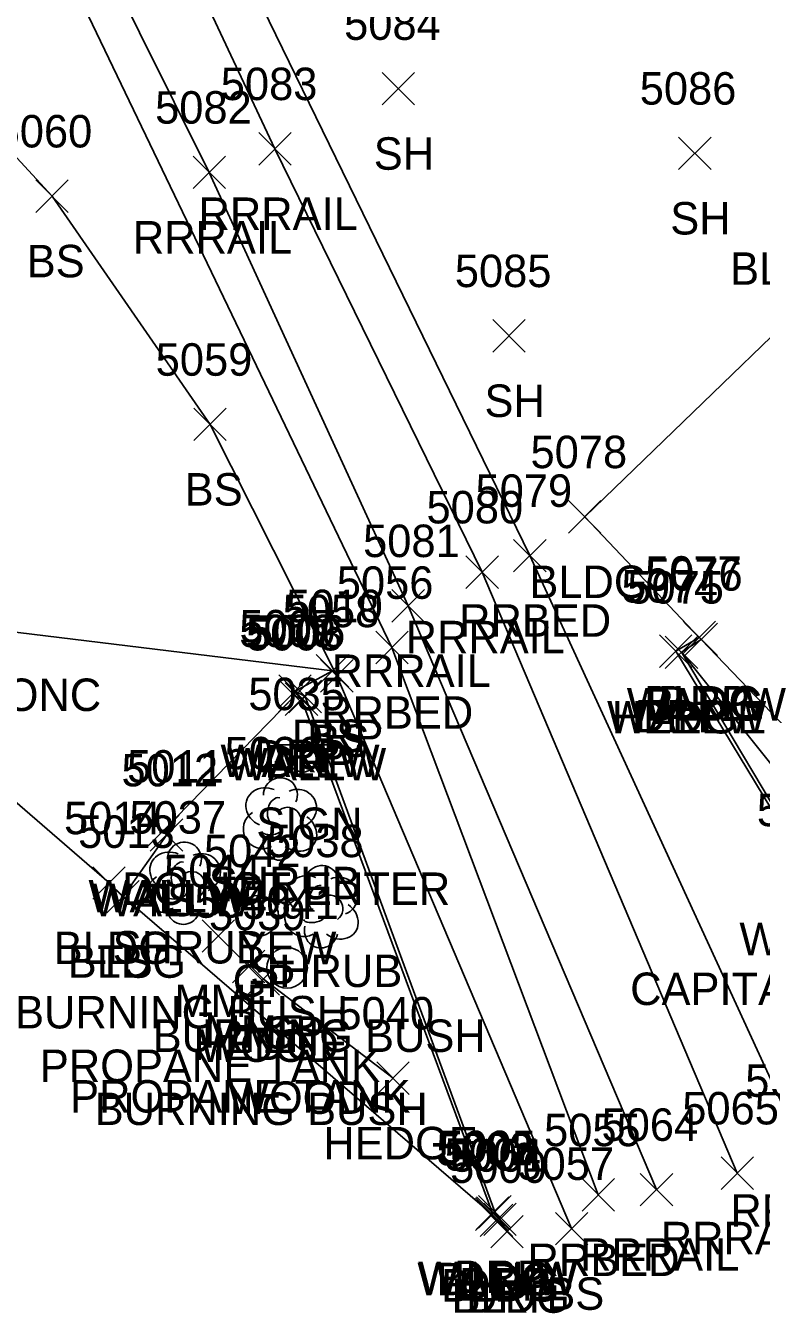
# Model space of a CAD drawing. Extents: x 1618146 to 1620418, y 640749 to 641927.
# Drawn here: x 1620302.7 to 1620347.9, y 640851.8 to 640931.1 of the extents above; entities that cross this region are included whole.
import ezdxf

# ---------------------------------------------------------------- set-up
doc = ezdxf.new("R2010")
doc.units = 0
for name, color, linetype in [('L_A', 7, 'Continuous'), ('L_C', 7, 'Continuous'), ('L_I', 7, 'Continuous'), ('L_TIC', 7, 'Continuous'), ('LAHR', 7, 'Continuous'), ('LBC', 7, 'Continuous'), ('LELB', 7, 'Continuous'), ('LSH', 7, 'Continuous'), ('LW', 7, 'Continuous'), ('R_A', 7, 'Continuous'), ('R_C', 7, 'Continuous'), ('R_I', 7, 'Continuous'), ('R_TIC', 7, 'Continuous'), ('RDP', 7, 'Continuous'), ('RGP', 7, 'Continuous'), ('RR', 7, 'Continuous'), ('RRB', 7, 'Continuous'), ('S_A', 7, 'Continuous'), ('S_C', 7, 'Continuous'), ('S_I', 7, 'Continuous'), ('SSGN', 7, 'Continuous')]:
    doc.layers.add(name, color=color, linetype=linetype)

msp = doc.modelspace()

# ---------------------------------------------------------------- linework, layer by layer
at = {"layer": 'L_TIC'}
for points in [[(1620324.595, 640926.259), (1620326.595, 640928.259)], [(1620326.595, 640926.259), (1620324.595, 640928.259)], [(1620342.854, 640922.27), (1620344.854, 640924.27)], [(1620344.854, 640922.27), (1620342.854, 640924.27)], [(1620303.27, 640919.632), (1620305.27, 640921.632)], [(1620305.27, 640919.632), (1620303.27, 640921.632)], [(1620331.413, 640911.029), (1620333.413, 640913.029)], [(1620333.413, 640911.029), (1620331.413, 640913.029)], [(1620313, 640905.57), (1620315, 640907.57)], [(1620315, 640905.57), (1620313, 640907.57)], [(1620336.076, 640899.875), (1620338.076, 640901.875)], [(1620338.076, 640899.875), (1620336.076, 640901.875)], [(1620343.131, 640892.451), (1620345.131, 640894.451)], [(1620345.131, 640892.451), (1620343.131, 640894.451)], [(1620343.245, 640892.328), (1620345.245, 640894.328)], [(1620345.245, 640892.328), (1620343.245, 640894.328)], [(1620343.245, 640892.328), (1620345.245, 640894.328)], [(1620345.245, 640892.328), (1620343.245, 640894.328)], [(1620342.033, 640891.533), (1620344.033, 640893.533)], [(1620344.033, 640891.533), (1620342.033, 640893.533)], [(1620342.033, 640891.533), (1620344.033, 640893.533)], [(1620344.033, 640891.533), (1620342.033, 640893.533)], [(1620320.542, 640890.388), (1620322.542, 640892.388)], [(1620322.542, 640890.388), (1620320.542, 640892.388)], [(1620320.811, 640890.079), (1620322.811, 640892.079)], [(1620322.811, 640890.079), (1620320.811, 640892.079)], [(1620318.222, 640888.851), (1620320.222, 640890.851)], [(1620320.222, 640888.851), (1620318.222, 640890.851)], [(1620318.631, 640888.646), (1620320.631, 640890.646)], [(1620320.631, 640888.646), (1620318.631, 640890.646)], [(1620310.095, 640880.505), (1620312.095, 640882.505)], [(1620312.095, 640880.505), (1620310.095, 640882.505)], [(1620310.319, 640880.275), (1620312.319, 640882.275)], [(1620312.319, 640880.275), (1620310.319, 640882.275)], [(1620310.319, 640880.275), (1620312.319, 640882.275)], [(1620312.319, 640880.275), (1620310.319, 640882.275)], [(1620306.781, 640877.325), (1620308.781, 640879.325)], [(1620308.781, 640877.325), (1620306.781, 640879.325)], [(1620307.647, 640876.482), (1620309.647, 640878.482)], [(1620309.647, 640876.482), (1620307.647, 640878.482)], [(1620307.647, 640876.482), (1620309.647, 640878.482)], [(1620309.647, 640876.482), (1620307.647, 640878.482)], [(1620313.515, 640874.06), (1620315.515, 640876.06)], [(1620315.515, 640874.06), (1620313.515, 640876.06)], [(1620315.379, 640872.178), (1620317.379, 640874.178)], [(1620317.379, 640872.178), (1620315.379, 640874.178)], [(1620316.279, 640871.411), (1620318.279, 640873.411)], [(1620318.279, 640871.411), (1620316.279, 640873.411)], [(1620324.273, 640865.299), (1620326.273, 640867.299)], [(1620326.273, 640865.299), (1620324.273, 640867.299)], [(1620330.352, 640856.923), (1620332.352, 640858.923)], [(1620332.352, 640856.923), (1620330.352, 640858.923)], [(1620330.352, 640856.923), (1620332.352, 640858.923)], [(1620332.352, 640856.923), (1620330.352, 640858.923)], [(1620330.403, 640856.988), (1620332.403, 640858.988)], [(1620332.403, 640856.988), (1620330.403, 640858.988)], [(1620330.644, 640856.534), (1620332.644, 640858.534)], [(1620332.644, 640856.534), (1620330.644, 640858.534)], [(1620331.284, 640855.845), (1620333.284, 640857.845)], [(1620333.284, 640855.845), (1620331.284, 640857.845)], [(1620335.269, 640856.028), (1620337.269, 640858.028)], [(1620337.269, 640856.028), (1620335.269, 640858.028)]]:
    msp.add_lwpolyline(points, dxfattribs=at)
at = {"layer": 'LAHR'}
for points in [[(1620358.877, 640864.536), (1620354.87, 640877.733), (1620343.033, 640892.533)], [(1620317.279, 640872.411), (1620325.273, 640866.299)]]:
    msp.add_lwpolyline(points, dxfattribs=at)
at = {"layer": 'LBC'}
for points in [[(1620357.188, 640879.802), (1620344.245, 640893.328), (1620344.131, 640893.451), (1620337.076, 640900.875), (1620357.059, 640920.172), (1620360.646, 640923.652), (1620363.762, 640926.588), (1620367.036, 640929.694)], [(1620332.284, 640856.845), (1620331.644, 640857.534), (1620331.352, 640857.923), (1620308.647, 640877.482), (1620307.781, 640878.325), (1620291.579, 640892.357), (1620287.512, 640896.159), (1620282.611, 640900.197), (1620282.333, 640900.011), (1620250.859, 640862.217)]]:
    msp.add_lwpolyline(points, dxfattribs=at)
at = {"layer": 'LELB'}
for points in [[(1620336.269, 640857.028), (1620321.811, 640891.079), (1620314, 640906.57), (1620304.27, 640920.632), (1620296.264, 640929.294)], [(1620311.319, 640881.275), (1620308.647, 640877.482)]]:
    msp.add_lwpolyline(points, dxfattribs=at)
at = {"layer": 'LSH'}
for p, q in [((1620318.291, 640882.32), (1620318.291, 640882.32)), ((1620318.291, 640882.32), (1620318.291, 640882.32)), ((1620312.376, 640878.362), (1620312.376, 640878.362)), ((1620312.376, 640878.362), (1620312.376, 640878.362)), ((1620320.848, 640876.912), (1620320.848, 640876.912)), ((1620320.848, 640876.912), (1620320.848, 640876.912))]:
    msp.add_line(p, q, dxfattribs=at)
for centre in [(1620318.337, 640883.754), (1620312.422, 640879.796), (1620320.895, 640878.346)]:
    msp.add_arc(centre, 1.047, 335.52715, 180.95627, dxfattribs=at)
for centre, major_axis, ratio, start_param, end_param in [((1620317.499, 640882.987), (1.21, -0.512), 0.895232, 1.570796, 4.712389), ((1620319.332, 640882.904), (-1.141, -0.483), 0.949671, 1.570796, 4.712389), ((1620318.082, 640882.778), (-0.208, -0.792), 0.645439, 3.141593, 6.283185), ((1620318.791, 640882.153), (-0.5, 0.667), 0.989748, 3.141593, 6.283185), ((1620317.207, 640881.612), (0.584, -1.042), 0.959034, 3.141593, 6.283185), ((1620319.291, 640881.487), (-1.09, 0.792), 0.841452, 1.570796, 4.712389), ((1620317.832, 640881.57), (-0.625, -0.083), 0.423636, 0, 3.141593), ((1620311.584, 640879.028), (1.21, -0.512), 0.895232, 1.570796, 4.712389), ((1620313.417, 640878.945), (-1.141, -0.483), 0.949671, 1.570796, 4.712389), ((1620318.291, 640880.82), (0.265, 1.061), 0.942809, 1.570796, 4.712389), ((1620312.167, 640878.82), (-0.208, -0.792), 0.645439, 3.141593, 6.283185), ((1620311.292, 640877.653), (0.584, -1.042), 0.959034, 3.141593, 6.283185), ((1620312.876, 640878.195), (-0.5, 0.667), 0.989748, 3.141593, 6.283185), ((1620320.056, 640877.578), (1.21, -0.512), 0.895232, 1.570796, 4.712389), ((1620321.89, 640877.495), (-1.141, -0.483), 0.949671, 1.570796, 4.712389), ((1620313.376, 640877.529), (-1.09, 0.792), 0.841452, 1.570796, 4.712389), ((1620320.64, 640877.37), (-0.208, -0.792), 0.645439, 3.141593, 6.283185), ((1620312.376, 640876.862), (0.265, 1.061), 0.942809, 1.570796, 4.712389), ((1620311.917, 640877.612), (-0.625, -0.083), 0.423636, 0, 3.141593), ((1620319.765, 640876.203), (0.584, -1.042), 0.959034, 3.141593, 6.283185), ((1620321.348, 640876.745), (-0.5, 0.667), 0.989748, 3.141593, 6.283185), ((1620321.848, 640876.079), (-1.09, 0.792), 0.841452, 1.570796, 4.712389), ((1620320.848, 640875.412), (0.265, 1.061), 0.942809, 1.570796, 4.712389), ((1620320.39, 640876.162), (-0.625, -0.083), 0.423636, 0, 3.141593)]:
    msp.add_ellipse(centre, major_axis=major_axis, ratio=ratio, start_param=start_param, end_param=end_param, dxfattribs=at)
at = {"layer": 'LW'}
for points in [[(1620356.45, 640863.732), (1620351.183, 640878.874), (1620343.033, 640892.533), (1620344.245, 640893.328)], [(1620331.352, 640857.923), (1620331.403, 640857.988), (1620319.631, 640889.646), (1620319.222, 640889.851), (1620311.095, 640881.505), (1620311.319, 640881.275)]]:
    msp.add_lwpolyline(points, dxfattribs=at)
at = {"layer": 'R_TIC'}
for points in [[(1620317, 640922.549), (1620319, 640924.549)], [(1620319, 640922.549), (1620317, 640924.549)], [(1620312.957, 640921.099), (1620314.957, 640923.099)], [(1620314.957, 640921.099), (1620312.957, 640923.099)], [(1620332.696, 640897.491), (1620334.696, 640899.491)], [(1620334.696, 640897.491), (1620332.696, 640899.491)], [(1620329.756, 640896.472), (1620331.756, 640898.472)], [(1620331.756, 640896.472), (1620329.756, 640898.472)], [(1620325.199, 640894.398), (1620327.199, 640896.398)], [(1620327.199, 640894.398), (1620325.199, 640896.398)], [(1620324.201, 640891.825), (1620326.201, 640893.825)], [(1620326.201, 640891.825), (1620324.201, 640893.825)], [(1620343.131, 640892.451), (1620345.131, 640894.451)], [(1620345.131, 640892.451), (1620343.131, 640894.451)], [(1620341.674, 640891.599), (1620343.674, 640893.599)], [(1620343.674, 640891.599), (1620341.674, 640893.599)], [(1620320.542, 640890.388), (1620322.542, 640892.388)], [(1620322.542, 640890.388), (1620320.542, 640892.388)], [(1620318.237, 640889.142), (1620320.237, 640891.142)], [(1620320.237, 640889.142), (1620318.237, 640891.142)], [(1620318.856, 640888.812), (1620320.856, 640890.812)], [(1620320.856, 640888.812), (1620318.856, 640890.812)], [(1620345.466, 640859.448), (1620347.466, 640861.448)], [(1620347.466, 640859.448), (1620345.466, 640861.448)], [(1620336.907, 640858.107), (1620338.907, 640860.107)], [(1620338.907, 640858.107), (1620336.907, 640860.107)], [(1620340.494, 640858.435), (1620342.494, 640860.435)], [(1620342.494, 640858.435), (1620340.494, 640860.435)], [(1620330.536, 640857.064), (1620332.536, 640859.064)], [(1620332.536, 640857.064), (1620330.536, 640859.064)], [(1620330.853, 640856.601), (1620332.853, 640858.601)], [(1620332.853, 640856.601), (1620330.853, 640858.601)], [(1620331.284, 640855.845), (1620333.284, 640857.845)], [(1620333.284, 640855.845), (1620331.284, 640857.845)]]:
    msp.add_lwpolyline(points, dxfattribs=at)
at = {"layer": 'RDP'}
for points in [[(1620332.284, 640856.845), (1620331.853, 640857.601), (1620331.536, 640858.064), (1620319.856, 640889.812), (1620319.237, 640890.142), (1620321.542, 640891.388), (1620293.744, 640894.779)], [(1620356.19, 640863.549), (1620351.013, 640878.823), (1620342.674, 640892.599), (1620344.131, 640893.451)]]:
    msp.add_lwpolyline(points, dxfattribs=at)
at = {"layer": 'RGP'}
for p, q in [((1620316.964, 640876.299), (1620316.964, 640876.299)), ((1620318.746, 640873.097), (1620318.746, 640873.097))]:
    msp.add_line(p, q, dxfattribs=at)
for centre, radius in [((1620316.964, 640876.299), 1.25), ((1620316.964, 640876.299), 0.0833), ((1620318.746, 640873.097), 1.25), ((1620318.746, 640873.097), 0.0833)]:
    msp.add_circle(centre, radius, dxfattribs=at)
at = {"layer": 'RR'}
for points in [[(1620346.466, 640860.448), (1620330.756, 640897.472), (1620318, 640923.549), (1620306.673, 640947.652), (1620300.323, 640960.311), (1620293.935, 640972.261), (1620285.981, 640987.098), (1620281.456, 640995.25), (1620258.355, 641033.113), (1620241.318, 641059.633), (1620217.616, 641094.164), (1620201.563, 641115.97), (1620192.149, 641127.788), (1620168.312, 641155.994)], [(1620341.494, 640859.435), (1620326.199, 640895.398), (1620313.957, 640922.099), (1620303.215, 640943.7), (1620296.609, 640956.784), (1620290.437, 640967.965), (1620282.921, 640982.142), (1620278.195, 640990.782), (1620254.107, 641030.531), (1620237.651, 641056.889), (1620213.711, 641091.105), (1620198.15, 641113.288), (1620190.752, 641121.585), (1620164.758, 641152.663)]]:
    msp.add_lwpolyline(points, dxfattribs=at)
at = {"layer": 'RRB'}
for points in [[(1620350.399, 640862.151), (1620333.696, 640898.491), (1620311.058, 640944.945)], [(1620337.907, 640859.107), (1620325.201, 640892.825), (1620303.727, 640937.553)]]:
    msp.add_lwpolyline(points, dxfattribs=at)
at = {"layer": 'SSGN'}
for p, q in [((1620318.067, 640886.822), (1620321.401, 640886.822)), ((1620319.714, 640885.988), (1620319.714, 640885.988))]:
    msp.add_line(p, q, dxfattribs=at)
msp.add_circle((1620319.714, 640885.988), 0.833, dxfattribs=at)

# ---------------------------------------------------------------- texts
at = {"layer": 'L_A'}
for s, p in [('SH', (1620324.083, 640922.259)), ('SH', (1620342.342, 640918.27)), ('BS', (1620302.711, 640915.632)), ('BLDG STPC ST', (1620346.028, 640915.172)), ('SH', (1620330.902, 640907.029)), ('BS', (1620312.441, 640901.57)), ('BLDG', (1620333.666, 640895.875)), ('WALLW', (1620339.662, 640888.328)), ('BLDG', (1620340.722, 640888.451)), ('BLDG', (1620340.835, 640888.328)), ('WALLW', (1620338.45, 640887.533)), ('HEDGE', (1620338.734, 640887.533)), ('BS', (1620319.983, 640886.388)), ('BS', (1620320.252, 640886.079)), ('WALLW', (1620314.64, 640884.851)), ('WALLW', (1620315.049, 640884.646)), ('SHRUB', (1620313.92, 640877.32)), ('WALLW', (1620306.513, 640876.505)), ('WALLW', (1620306.737, 640876.275)), ('TS', (1620309.729, 640876.275)), ('WALLW', (1620346.6, 640873.874)), ('BLDG', (1620304.372, 640873.325)), ('SHRUB', (1620308.006, 640873.362)), ('BLDG', (1620305.237, 640872.482)), ('TS', (1620307.056, 640872.482)), ('SHRUB', (1620316.478, 640871.912)), ('MMF', (1620311.799, 640870.06)), ('MMF', (1620313.662, 640868.178)), ('HEDGE', (1620312.98, 640867.411)), ('HEDGE', (1620320.974, 640861.299)), ('WALLW', (1620326.77, 640852.923)), ('WALLW', (1620326.821, 640852.988)), ('BLDG', (1620327.943, 640852.923)), ('BLDG', (1620328.234, 640852.534)), ('BLDG', (1620328.875, 640851.845)), ('BS', (1620334.71, 640852.028))]:
    msp.add_text(s, height=2, dxfattribs=at).set_placement(p)
at = {"layer": 'L_C'}
for s, p in [('YEW', (1620315.692, 640873.32)), ('CAPITAL DRY CLEANING', (1620339.873, 640870.802)), ('BURNING BUSH', (1620301.998, 640869.362)), ('BURNING BUSH', (1620310.47, 640867.912)), ('PROPANE TANK', (1620303.523, 640866.06)), ('PROPANE TANK', (1620305.387, 640864.178)), ('BURNING BUSH', (1620306.901, 640863.411))]:
    msp.add_text(s, height=2, dxfattribs=at).set_placement(p)
at = {"layer": 'L_I'}
for s, p in [('5084', (1620322.257, 640930.259)), ('5086', (1620340.461, 640926.27)), ('5060', (1620300.798, 640923.632)), ('5085', (1620329.075, 640915.029)), ('5059', (1620310.654, 640909.57)), ('5078', (1620333.737, 640903.875)), ('5077', (1620340.793, 640896.451)), ('5076', (1620340.851, 640896.328)), ('5076', (1620340.851, 640896.328)), ('5075', (1620339.694, 640895.533)), ('5075', (1620339.694, 640895.533)), ('5010', (1620318.684, 640894.388)), ('5058', (1620318.472, 640894.079)), ('5009', (1620315.797, 640892.851)), ('5008', (1620316.214, 640892.646)), ('5036', (1620314.897, 640885.32)), ('5012', (1620308.548, 640884.275)), ('5012', (1620308.548, 640884.275)), ('5011', (1620308.891, 640884.505)), ('5014', (1620305.01, 640881.325)), ('5037', (1620309.037, 640881.362)), ('5013', (1620305.875, 640880.482)), ('5013', (1620305.875, 640880.482)), ('5038', (1620317.51, 640879.912)), ('5044', (1620311.177, 640878.06)), ('5043', (1620313.04, 640876.178)), ('5039', (1620313.932, 640875.411)), ('5040', (1620321.848, 640869.299)), ('5002', (1620327.935, 640860.923)), ('5002', (1620327.935, 640860.923)), ('5003', (1620327.986, 640860.988)), ('5001', (1620328.793, 640860.534)), ('5057', (1620332.931, 640860.028)), ('5000', (1620328.78, 640859.845))]:
    msp.add_text(s, height=2, dxfattribs=at).set_placement(p)
at = {"layer": 'R_A'}
for s, p in [('RRRAIL', (1620313.292, 640918.549)), ('RRRAIL', (1620309.248, 640917.099)), ('RRBED', (1620329.342, 640893.491)), ('RRRAIL', (1620326.047, 640892.472)), ('RRRAIL', (1620321.49, 640890.398)), ('RRBED', (1620320.846, 640887.825)), ('DRP', (1620341.619, 640888.451)), ('DRP', (1620340.162, 640887.599)), ('DRP', (1620319.03, 640886.388)), ('DRP', (1620316.725, 640885.142)), ('DRP', (1620317.344, 640884.812)), ('GP', (1620315.398, 640871.299)), ('GP', (1620317.18, 640868.097)), ('RRBED', (1620346.045, 640857.151)), ('RRRAIL', (1620341.757, 640855.448)), ('RRBED', (1620333.553, 640854.107)), ('RRRAIL', (1620336.786, 640854.435)), ('DRP', (1620329.024, 640853.064)), ('DRP', (1620329.341, 640852.601)), ('DRP', (1620329.772, 640851.845))]:
    msp.add_text(s, height=2, dxfattribs=at).set_placement(p)
at = {"layer": 'R_C'}
for s, p in [('STEEL W/CONC', (1620286.942, 640888.915)), ('WOOD', (1620313.319, 640867.299)), ('WOOD', (1620315.101, 640864.097))]:
    msp.add_text(s, height=2, dxfattribs=at).set_placement(p)
at = {"layer": 'R_I'}
for s, p in [('5083', (1620314.662, 640926.549)), ('5082', (1620310.619, 640925.099)), ('5079', (1620330.35, 640901.491)), ('5080', (1620327.331, 640900.472)), ('5081', (1620323.427, 640898.398)), ('5056', (1620321.807, 640895.825)), ('5077', (1620340.793, 640896.451)), ('5074', (1620339.336, 640895.599)), ('5010', (1620318.684, 640894.388)), ('5007', (1620315.819, 640893.142)), ('5006', (1620316.383, 640892.812)), ('5073', (1620347.674, 640881.823)), ('5042', (1620313.626, 640879.299)), ('5041', (1620315.975, 640876.097)), ('5066', (1620346.958, 640865.151)), ('5065', (1620343.08, 640863.448)), ('5064', (1620338.108, 640862.435)), ('5055', (1620334.569, 640862.107)), ('5005', (1620328.119, 640861.064)), ('5004', (1620328.436, 640860.601)), ('5000', (1620328.78, 640859.845))]:
    msp.add_text(s, height=2, dxfattribs=at).set_placement(p)
at = {"layer": 'S_A'}
msp.add_text('SIGN', height=2, dxfattribs=at).set_placement((1620316.852, 640880.968))
at = {"layer": 'S_C'}
msp.add_text('DO NOT ENTER', height=2, dxfattribs=at).set_placement((1620308.585, 640876.968))
at = {"layer": 'S_I'}
msp.add_text('5035', height=2, dxfattribs=at).set_placement((1620316.356, 640888.968))

doc.saveas('drawing.dxf')
